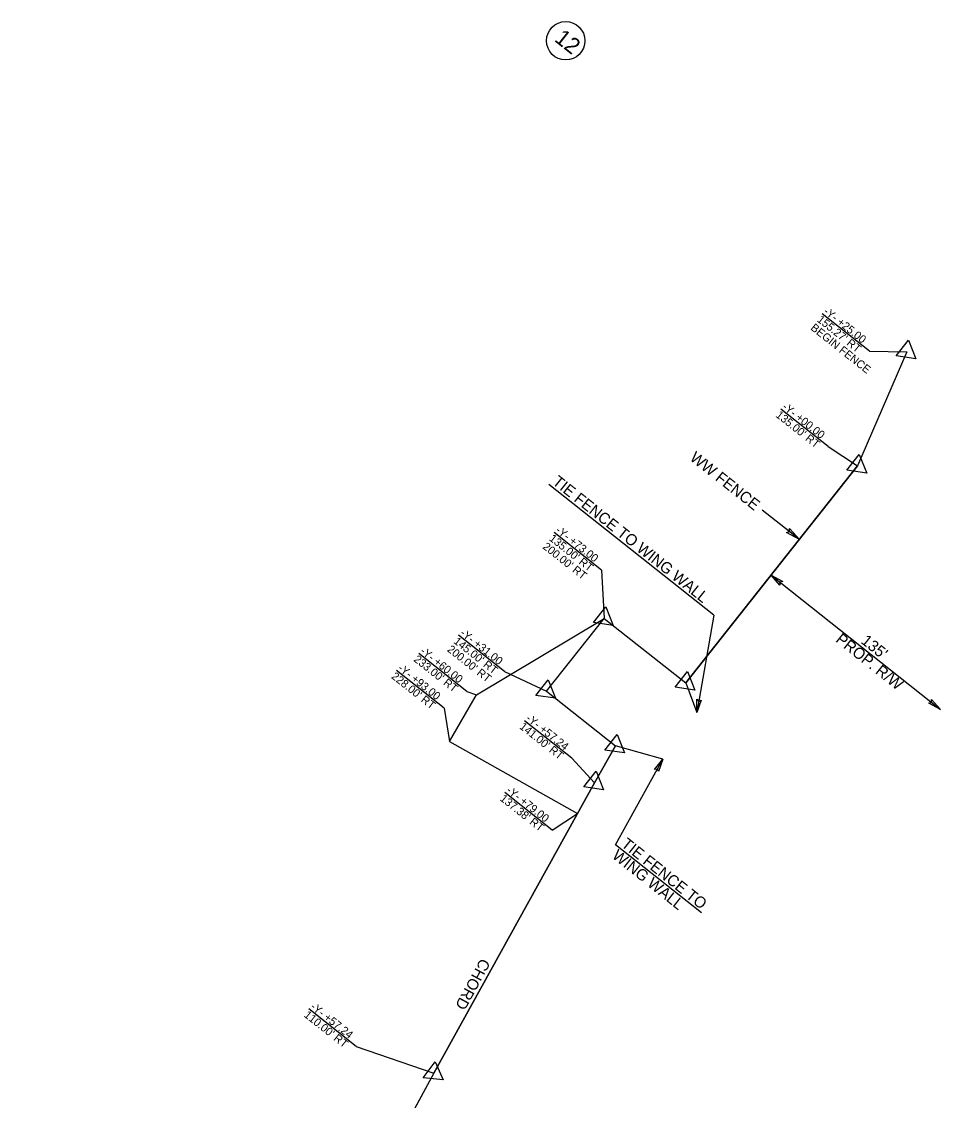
# Model space of a CAD drawing. Extents: x 1779796 to 1783527, y 810952 to 815815.
# Drawn here: x 1781075 to 1781649, y 812940 to 813614 of the extents above; entities that cross this region are included whole.
import ezdxf

# ---------------------------------------------------------------- set-up
doc = ezdxf.new("R2010")
doc.units = 0
for name, color, linetype in [('Prop Dimension', 7, 'Continuous'), ('Prop Dimension Text', 7, 'Continuous'), ('Prop Easement Temporary Drainage', 7, 'Continuous'), ('Prop Easement Temporary Drainage Station Offsets', 7, 'Continuous'), ('Prop Fence Woven Wire', 7, 'Continuous'), ('Prop Parcel Number CELL', 7, 'Continuous'), ('Prop Parcel Number Text', 7, 'Continuous'), ('Prop ROW Marker CELL', 7, 'Continuous'), ('Prop ROW RW CA Lines', 7, 'Continuous'), ('Prop ROW Station Offsets', 7, 'Continuous'), ('Prop Terminator CELL', 7, 'Continuous')]:
    doc.layers.add(name, color=color, linetype=linetype)

msp = doc.modelspace()

# ---------------------------------------------------------------- linework, layer by layer
at = {"layer": 'Prop Dimension'}
for p, q in [((1781507.6, 813243.37), (1781404.41, 813325.06)), ((1781560.97, 813290.63), (1781537.76, 813309.01)), ((1781543.25, 813268.24), (1781649.09, 813184.44)), ((1781507.6, 813243.37), (1781496.84, 813182.46)), ((1781446.14, 813099.74), (1781475.66, 813153.38)), ((1781499.74, 813057.31), (1781446.14, 813099.74))]:
    msp.add_line(p, q, dxfattribs=at)
at = {"layer": 'Prop Easement Temporary Drainage'}
for p, q in [((1781359.14, 813193.58), (1781439.02, 813241.3)), ((1781342.4, 813164.34), (1781359.14, 813193.58)), ((1781342.4, 813164.34), (1781422.27, 813119.27))]:
    msp.add_line(p, q, dxfattribs=at)
at = {"layer": 'Prop Easement Temporary Drainage Station Offsets'}
for p, q in [((1781353.24, 813195.56), (1781323.11, 813219.42)), ((1781338.9, 813185.24), (1781309.12, 813208.81)), ((1781353.24, 813195.56), (1781359.14, 813193.58)), ((1781338.9, 813185.24), (1781342.4, 813164.34)), ((1781406.56, 813109.01), (1781376.99, 813132.43)), ((1781406.56, 813109.01), (1781422.27, 813119.27))]:
    msp.add_line(p, q, dxfattribs=at)
at = {"layer": 'Prop Fence Woven Wire'}
for p, q in [((1781628.03, 813407.98), (1781597.36, 813336.59)), ((1781597.36, 813336.59), (1781489.98, 813200.96)), ((1781489.98, 813200.96), (1781496.84, 813182.46)), ((1781446.14, 813161.69), (1781432.99, 813138.63)), ((1781475.66, 813153.38), (1781446.14, 813161.69)), ((1781432.99, 813138.63), (1781332.56, 812957.08)), ((1781332.56, 812957.08), (1781074.95, 812482.41))]:
    msp.add_line(p, q, dxfattribs=at)
at = {"layer": 'Prop Parcel Number CELL'}
msp.add_line((1781414.95, 813602.27), (1781414.95, 813602.27), dxfattribs=at)
msp.add_circle((1781414.95, 813602.27), 12, dxfattribs=at)
at = {"layer": 'Prop ROW Marker CELL'}
for p, q in [((1781628.03, 813407.98), (1781628.03, 813407.98)), ((1781597.36, 813336.59), (1781597.36, 813336.59)), ((1781439.02, 813241.3), (1781439.02, 813241.3)), ((1781489.98, 813200.96), (1781489.98, 813200.96)), ((1781403.02, 813195.83), (1781403.02, 813195.83)), ((1781446.14, 813161.69), (1781446.14, 813161.69)), ((1781432.99, 813138.63), (1781432.99, 813138.63)), ((1781332.56, 812957.08), (1781332.56, 812957.08))]:
    msp.add_line(p, q, dxfattribs=at)
for points in [[(1781633.68, 813403.5), (1781621.34, 813405.31), (1781629.06, 813415.11)], [(1781603.02, 813332.12), (1781590.67, 813333.93), (1781598.4, 813343.73)], [(1781444.67, 813236.83), (1781432.33, 813238.64), (1781440.05, 813248.44)], [(1781495.63, 813196.48), (1781483.29, 813198.3), (1781491.01, 813208.09)], [(1781408.67, 813191.35), (1781396.33, 813193.17), (1781404.05, 813202.97)], [(1781451.79, 813157.21), (1781439.45, 813159.03), (1781447.17, 813168.83)], [(1781438.64, 813134.16), (1781426.29, 813135.97), (1781434.02, 813145.77)], [(1781325.97, 812954.15), (1781333.31, 812964.24), (1781338.4, 812952.85)]]:
    msp.add_lwpolyline(points, close=True, dxfattribs=at)
at = {"layer": 'Prop ROW RW CA Lines'}
for p, q in [((1781628.03, 813407.98), (1781597.36, 813336.59)), ((1781489.98, 813200.96), (1781597.36, 813336.59)), ((1781403.02, 813195.83), (1781439.02, 813241.3)), ((1781439.02, 813241.3), (1781489.98, 813200.96)), ((1781403.02, 813195.83), (1781446.14, 813161.69))]:
    msp.add_line(p, q, dxfattribs=at)
for points in [[(1781432.99, 813138.63), (1781446.14, 813161.69)], [(1781332.56, 812957.08), (1781432.99, 813138.63)], [(1781332.56, 812957.08), (1781074.95, 812482.41)]]:
    msp.add_lwpolyline(points, dxfattribs=at)
at = {"layer": 'Prop ROW Station Offsets'}
for p, q in [((1781604.75, 813408.26), (1781575.13, 813431.72)), ((1781578.93, 813348.65), (1781549.31, 813372.1)), ((1781437.36, 813271.52), (1781407.74, 813294.97)), ((1781376.73, 813208.04), (1781348.05, 813230.75)), ((1781418.76, 813153.96), (1781389.19, 813177.38)), ((1781284.11, 812973.82), (1781254.54, 812997.23))]:
    msp.add_line(p, q, dxfattribs=at)
for points in [[(1781604.75, 813408.26), (1781628.03, 813407.98)], [(1781578.93, 813348.65), (1781597.36, 813336.59)], [(1781437.36, 813271.52), (1781439.02, 813241.3)], [(1781376.73, 813208.04), (1781403.02, 813195.83)], [(1781418.76, 813153.96), (1781432.99, 813138.63)], [(1781284.11, 812973.82), (1781332.56, 812957.08)]]:
    msp.add_lwpolyline(points, dxfattribs=at)
at = {"layer": 'Prop Terminator CELL'}
for points in [[(1781554.88, 813297.43), (1781560.97, 813290.63), (1781552.88, 813294.99), (1781554.78, 813295.53)], [(1781548.73, 813262.12), (1781543.25, 813268.24), (1781550.53, 813264.31), (1781548.82, 813263.83)], [(1781499.63, 813190.19), (1781496.84, 813182.46), (1781496.84, 813190.73), (1781498.08, 813189.46)], [(1781643.61, 813190.56), (1781649.09, 813184.44), (1781641.81, 813188.37), (1781643.52, 813188.86)], [(1781470.53, 813146.95), (1781475.66, 813153.38), (1781472.99, 813145.55), (1781472.23, 813147.15)]]:
    msp.add_lwpolyline(points, close=True, dxfattribs=at)

# ---------------------------------------------------------------- texts
at = {"layer": 'Prop Dimension Text'}
for s, rotation, p in [('WW FENCE', 321.63093, (1781492, 813340.62)), ('TIE FENCE TO WING WALL', 321.52512, (1781406.16, 813325.63)), ('PROP. R/W', 321.52512, (1781583.11, 813227.11)), ("135'", 321.52512, (1781598.97, 813226.23)), ('TIE FENCE TO', 321.52512, (1781449.14, 813099.19)), ('WING WALL', 321.52512, (1781443.43, 813092)), ('CHORD', 241.54905, (1781362.01, 813029.32))]:
    msp.add_text(s, height=7, rotation=rotation, dxfattribs=at).set_placement(p)
at = {"layer": 'Prop Easement Temporary Drainage Station Offsets'}
for s, p in [("233.00' RT", (1781319.55, 813214.9)), ('-Y- +60.00', (1781323.59, 813220)), ('-Y- +93.00', (1781309.6, 813209.39)), ("228.00' RT", (1781305.57, 813204.29)), ("137.38' RT", (1781373.44, 813127.91)), ('-Y- +79.00', (1781377.47, 813133))]:
    msp.add_text(s, height=5, rotation=321.63093, dxfattribs=at).set_placement(p)
at = {"layer": 'Prop Parcel Number Text'}
msp.add_text('12', height=10, rotation=321.63093, dxfattribs=at).set_placement((1781407.32, 813602.44))
at = {"layer": 'Prop ROW Station Offsets'}
for s, p in [('-Y- +25.00', (1781575.61, 813432.29)), ("155.27' RT", (1781571.58, 813427.2)), ('BEGIN FENCE', (1781567.54, 813422.1)), ('-Y- +00.00', (1781549.79, 813372.68)), ("135.00' RT", (1781545.76, 813367.58)), ("135.00' RT", (1781404.19, 813290.45)), ('-Y- +73.00', (1781408.22, 813295.55)), ("200.00' RT", (1781400.15, 813285.35)), ('-Y- +31.00', (1781348.53, 813231.32)), ("145.00' RT", (1781344.49, 813226.23)), ("200.00' RT", (1781340.46, 813221.13)), ('-Y- +57.24', (1781389.67, 813177.95)), ("141.00' RT", (1781385.64, 813172.86)), ("110.00' RT", (1781250.98, 812992.71)), ('-Y- +57.24', (1781255.02, 812997.81))]:
    msp.add_text(s, height=5, rotation=321.63093, dxfattribs=at).set_placement(p)

doc.saveas('drawing.dxf')
